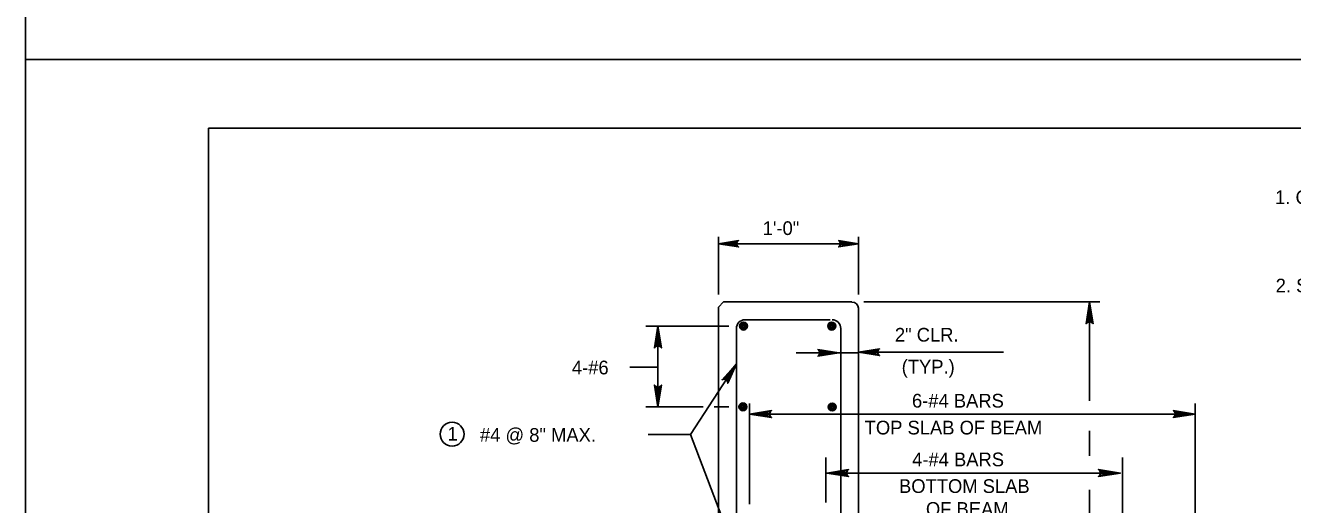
# Model space of a CAD drawing. Extents: x 642009 to 642864, y 298232 to 300014.
# Drawn here: x 642008.7 to 642285.5, y 298728.5 to 298833.3 of the extents above; entities that cross this region are included whole.
import ezdxf

# ---------------------------------------------------------------- set-up
doc = ezdxf.new("R2010")
doc.units = 0
for name, color, linetype in [('1', 7, 'Continuous'), ('2', 7, 'Continuous'), ('50', 7, 'Continuous'), ('PLT-BNDY', 7, 'Continuous')]:
    doc.layers.add(name, color=color, linetype=linetype)

# ---------------------------------------------------------------- blocks, each defined once
blk = doc.blocks.new('BAR')
at = {"layer": '50'}
for radius in [2, 1.5, 1, 0.5]:
    blk.add_circle((0, 0), radius, dxfattribs=at)

msp = doc.modelspace()

# ---------------------------------------------------------------- linework, layer by layer
at = {"layer": '1'}
for points in [[(642240.54, 298768.29), (642240.86, 298768.46), (642241.11, 298772.83), (642240.54, 298768.29), (642240.34, 298768.06), (642241.11, 298772.83), (642241.32, 298768.46), (642241.65, 298768.3), (642241.11, 298772.83), (642241.86, 298768.06), (642241.65, 298768.3)], [(642146.25, 298763.01), (642146.57, 298763.18), (642146.82, 298767.56), (642146.25, 298763.01), (642146.05, 298762.78), (642146.82, 298767.56), (642147.03, 298763.19), (642147.36, 298763.03), (642146.82, 298767.56), (642147.57, 298762.78), (642147.36, 298763.03)], [(642147.39, 298754.44), (642147.06, 298754.27), (642146.82, 298749.9), (642147.39, 298754.44), (642147.59, 298754.67), (642146.82, 298749.9), (642146.6, 298754.26), (642146.27, 298754.42), (642146.82, 298749.9), (642146.06, 298754.67), (642146.27, 298754.42)], [(642171.4, 298747.75), (642171.23, 298748.08), (642166.86, 298748.32), (642171.4, 298747.75), (642171.63, 298747.55), (642166.86, 298748.32), (642171.23, 298748.54), (642171.39, 298748.86), (642166.86, 298748.32), (642171.63, 298749.08), (642171.39, 298748.86)], [(642259.6, 298748.89), (642259.77, 298748.56), (642264.14, 298748.32), (642259.6, 298748.89), (642259.36, 298749.09), (642264.14, 298748.32), (642259.77, 298748.1), (642259.61, 298747.78), (642264.14, 298748.32), (642259.36, 298747.56), (642259.61, 298747.78)], [(642188.24, 298734.86), (642188.07, 298735.19), (642183.7, 298735.43), (642188.24, 298734.86), (642188.47, 298734.66), (642183.7, 298735.43), (642188.07, 298735.65), (642188.23, 298735.97), (642183.7, 298735.43), (642188.47, 298736.19), (642188.23, 298735.97)], [(642243.28, 298736), (642243.45, 298735.67), (642247.83, 298735.43), (642243.28, 298736), (642243.05, 298736.2), (642247.83, 298735.43), (642243.46, 298735.22), (642243.3, 298734.89), (642247.83, 298735.43), (642243.05, 298734.67), (642243.3, 298734.89)]]:
    msp.add_lwpolyline(points, dxfattribs=at)
msp.add_circle((642101.86, 298743.93), 2.61, dxfattribs=at)
at = {"layer": '2'}
for p, q in [((642048.66, 298246.82), (642048.66, 298810.82)), ((642048.66, 298810.82), (642834.66, 298810.82)), ((642160.07, 298774.44), (642160.07, 298787.06)), ((642190.65, 298774.44), (642190.65, 298787.06)), ((642160.07, 298785.56), (642190.65, 298785.56)), ((642161.11, 298772.83), (642160.07, 298771.67)), ((642189.19, 298772.83), (642161.11, 298772.83)), ((642191.77, 298772.83), (642243.35, 298772.83)), ((642241.11, 298751.21), (642241.11, 298772.83)), ((642160.07, 298771.67), (642160.07, 298669.76)), ((642190.65, 298771.5), (642190.65, 298666.31)), ((642144.17, 298767.56), (642162.28, 298767.56)), ((642146.82, 298767.56), (642146.82, 298749.9)), ((642163.97, 298703.05), (642163.97, 298767.05)), ((642165.85, 298768.93), (642184.45, 298768.93)), ((642186.76, 298703.05), (642186.76, 298767.05)), ((642190.65, 298761.7), (642177.01, 298761.7)), ((642190.65, 298761.83), (642222.28, 298761.83)), ((642140.67, 298758.61), (642146.82, 298758.61)), ((642153.94, 298743.88), (642163.97, 298759.27)), ((642166.86, 298750.64), (642166.86, 298728.65)), ((642264.14, 298750.64), (642264.14, 298720.9)), ((642144.17, 298749.9), (642156.73, 298749.9)), ((642159.12, 298749.9), (642162.28, 298749.9)), ((642264.14, 298748.32), (642166.86, 298748.32)), ((642241.11, 298739.21), (642241.11, 298744.68)), ((642144.7, 298743.88), (642153.94, 298743.88)), ((642170.97, 298699.21), (642153.94, 298743.88)), ((642183.48, 298738.81), (642183.48, 298728.95)), ((642248.32, 298738.81), (642248.32, 298685.35)), ((642247.83, 298735.43), (642183.7, 298735.43)), ((642241.11, 298687.5), (642241.11, 298731.74))]:
    msp.add_line(p, q, dxfattribs=at)
for points in [[(642164.22, 298785.04), (642164.07, 298785.34), (642160.07, 298785.56), (642164.22, 298785.04), (642164.44, 298784.86), (642160.07, 298785.56), (642164.07, 298785.76), (642164.21, 298786.05), (642160.07, 298785.56), (642164.44, 298786.25), (642164.21, 298786.05)], [(642186.5, 298786.08), (642186.65, 298785.78), (642190.65, 298785.56), (642186.5, 298786.08), (642186.29, 298786.26), (642190.65, 298785.56), (642186.66, 298785.36), (642186.51, 298785.06), (642190.65, 298785.56), (642186.29, 298784.87), (642186.51, 298785.06)], [(642181.97, 298762.24), (642182.14, 298761.93), (642186.33, 298761.7), (642181.97, 298762.24), (642181.75, 298762.44), (642186.33, 298761.7), (642182.14, 298761.49), (642181.99, 298761.18), (642186.33, 298761.7), (642181.75, 298760.97), (642181.99, 298761.18)], [(642195.01, 298761.29), (642194.85, 298761.6), (642190.65, 298761.83), (642195.01, 298761.29), (642195.24, 298761.09), (642190.65, 298761.83), (642194.85, 298762.04), (642195, 298762.35), (642190.65, 298761.83), (642195.24, 298762.56), (642195, 298762.35)], [(642161.13, 298755.92), (642161.48, 298755.88), (642163.97, 298759.27), (642161.13, 298755.92), (642160.85, 298755.84), (642163.97, 298759.27), (642161.85, 298755.65), (642162.03, 298755.35), (642163.97, 298759.27), (642162.08, 298755.04), (642162.03, 298755.35)]]:
    msp.add_lwpolyline(points, dxfattribs=at)
for centre, radius, start, end in [((642189.19, 298771.34), 1.47, 6.0088, 89.9998), ((642165.85, 298767.05), 1.88, 90, 180), ((642184.87, 298767.05), 1.88, 0, 90)]:
    msp.add_arc(centre, radius, start, end, dxfattribs=at)
at = {"layer": 'PLT-BNDY'}
for points in [[(642008.66, 299419.82), (642849.66, 299419.82), (642849.66, 298825.82), (642008.66, 298825.82)], [(642008.66, 298825.82), (642849.66, 298825.82), (642849.66, 298231.82), (642008.66, 298231.82)]]:
    msp.add_lwpolyline(points, close=True, dxfattribs=at)

# ---------------------------------------------------------------- block references
at = {"layer": '2', "xscale": 0.4303528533, "yscale": -0.4303528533, "rotation": 180}
for p in [(642165.51, 298767.56), (642165.38, 298749.9)]:
    msp.add_blockref('BAR', p, dxfattribs=at)
at = {"layer": '2', "xscale": 0.4303528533, "yscale": 0.4303528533}
for p in [(642184.79, 298767.56), (642184.88, 298749.86)]:
    msp.add_blockref('BAR', p, dxfattribs=at)

# ---------------------------------------------------------------- texts
at = {"layer": '2'}
for s, p in [('1. CONCRETE COVER:', (642281.62, 298794.23)), ('1\'-0"', (642169.71, 298787.47)), ('2. SPLICING OF LONGITUDINAL STEEL IS NOT ALLOWED.', (642281.75, 298774.91)), ('2" CLR.', (642198.58, 298764.16)), ('4-#6', (642128.03, 298757)), ('(TYP.)', (642200.06, 298757.18)), ('6-#4 BARS', (642202.31, 298749.74)), ('1', (642100.87, 298742.52)), ('#4 @ 8" MAX.', (642107.95, 298742.26)), ('TOP SLAB OF BEAM', (642191.98, 298743.86)), ('4-#4 BARS', (642202.35, 298736.9)), ('BOTTOM SLAB', (642199.48, 298731.07)), ('OF BEAM', (642205.36, 298726.07))]:
    msp.add_text(s, height=3, dxfattribs=at).set_placement(p)

doc.saveas('drawing.dxf')
